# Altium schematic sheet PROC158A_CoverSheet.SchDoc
size 431 x 279 mm; Date: Not shown in title block; ApprovedBy: Not shown in title block; CheckedBy: Not shown in title block; Author: Not shown in title block; CompanyName: Not shown in title block; Engineer: Not shown in title block; Organization: Not shown in title block; Address1: Not shown in title block; Address2: Not shown in title block; Address3: Not shown in title block; Address4: Not shown in title block; DocumentNumber: 1; Revision: Use project parameter SCH_Rev; SheetNumber: 1; SheetTotal: 24; PageSetup: Record=PageOptions¦CenterHorizontal=True¦CenterVertical=True¦PrintScale=1.00¦XCorrection=1.00¦YCorrection=1.00¦PrintKind=0¦BorderSize=5000000¦LeftOffset=0¦BottomOffset=0¦Orientation=2¦PaperLength=1000¦PaperWidth=1000¦Scale=100¦PaperSource=15¦PrintQuality=600¦MediaType=1¦DitherType=10¦PaperKind=Letter¦PrintScaleMode=1
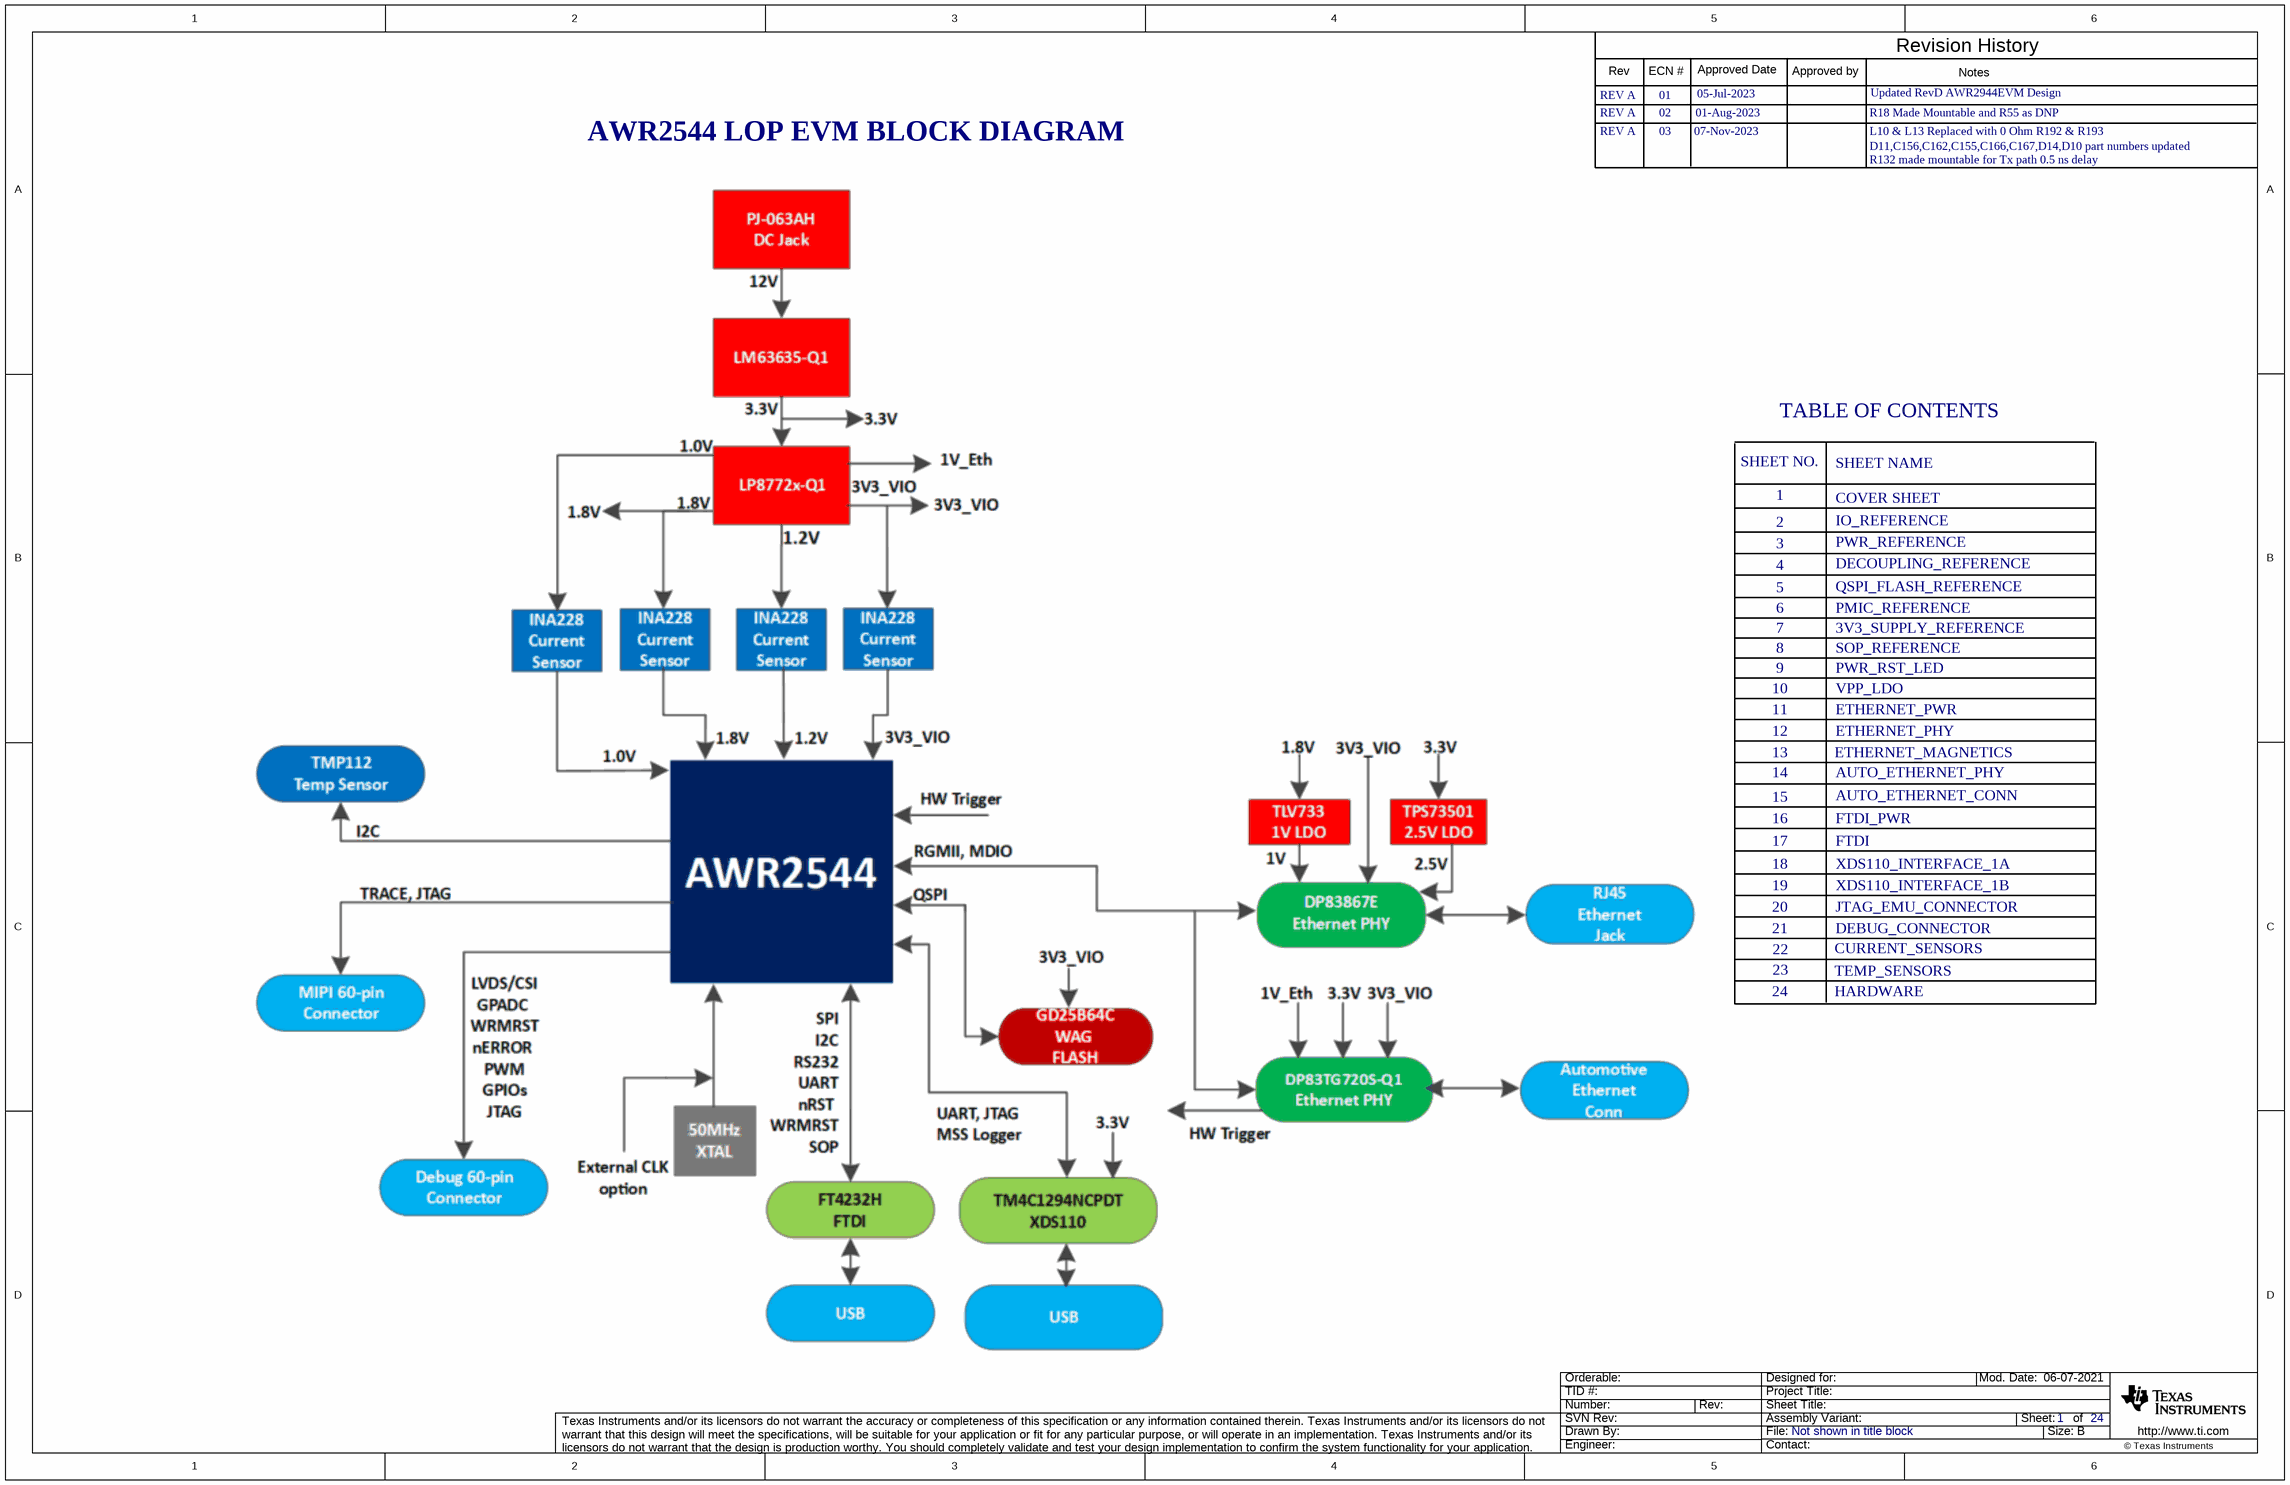
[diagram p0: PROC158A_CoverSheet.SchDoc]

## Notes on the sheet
- REV A
- Rev
- 01
- ECN #
- 05-Jul-2023
- Approved Date
- Approved by
- Updated RevD AWR2944EVM Design
- Revision History
- Notes
- AWR2544 LOP EVM BLOCK DIAGRAM
- 02
- 03
- 07-Nov-2023
- 01-Aug-2023
- R18 Made Mountable and R55 as DNP
- L10 & L13 Replaced with 0 Ohm R192 & R193
- D11,C156,C162,C155,C166,C167,D14,D10 part numbers updated
- R132 made mountable for Tx path 0.5 ns delay
- TABLE OF CONTENTS
- SHEET NO.
- 1
- SHEET NAME
- 2
- 3
- 4
- COVER SHEET
- IO_REFERENCE
- PWR_REFERENCE
- DECOUPLING_REFERENCE
- 5
- 7
- 6
- PMIC_REFERENCE
- QSPI_FLASH_REFERENCE
- 3V3_SUPPLY_REFERENCE
- 10
- 8
- 9
- PWR_RST_LED
- SOP_REFERENCE
- VPP_LDO
- 11
- 12
- 13
- ETHERNET_MAGNETICS
- ETHERNET_PWR
- ETHERNET_PHY
- 15
- 16
- 14
- FTDI_PWR
- AUTO_ETHERNET_CONN
- AUTO_ETHERNET_PHY
- 17
- 18
- 19
- XDS110_INTERFACE_1B
- XDS110_INTERFACE_1A
- FTDI
- 20
- 21
- 22
- CURRENT_SENSORS
- JTAG_EMU_CONNECTOR
- DEBUG_CONNECTOR
- 24
- 23
- HARDWARE
- TEMP_SENSORS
